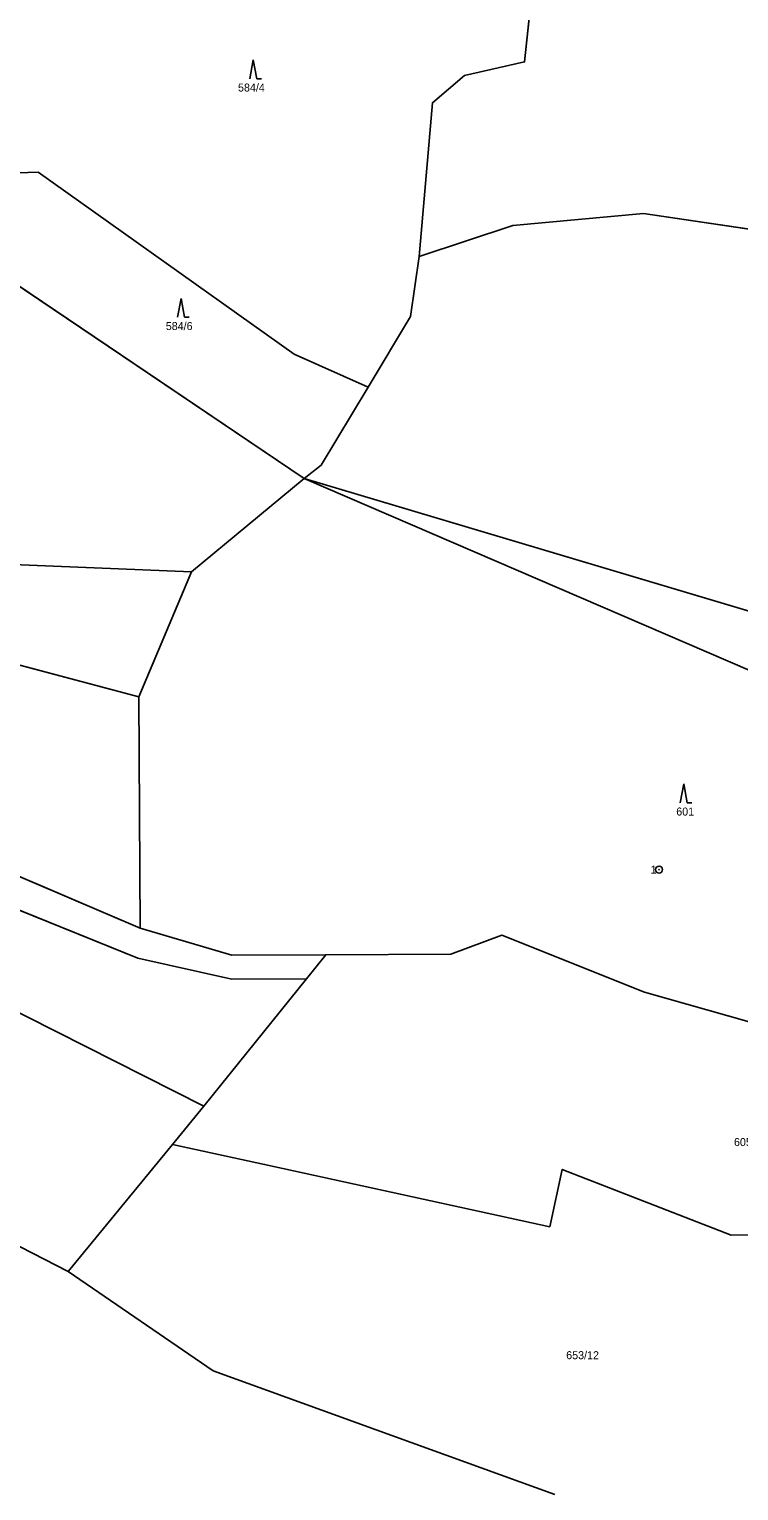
# Model space of a CAD drawing. Extents: x -760642 to -757221, y -1092371 to -1088855.
# Drawn here: x -759878.4 to -759727.7, y -1090551.6 to -1090241.2 of the extents above; entities that cross this region are included whole.
import ezdxf

# ---------------------------------------------------------------- set-up
doc = ezdxf.new("R2010")
doc.units = 0
for name, color, linetype in [('Vrstva 1', 7, 'Continuous'), ('Vrstva 17', 7, 'Continuous'), ('Vrstva 18', 7, 'Continuous'), ('Vrstva 24', 7, 'Continuous'), ('Vrstva 25', 7, 'Continuous'), ('Vrstva 30', 7, 'Continuous')]:
    doc.layers.add(name, color=color, linetype=linetype)

msp = doc.modelspace()

# ---------------------------------------------------------------- linework, layer by layer
at = {"layer": 'Vrstva 1'}
for p, q in [((-759770.83, -1090226.08), (-759773.19, -1090248.13)), ((-759785.94, -1090251.03), (-759792.77, -1090256.83)), ((-759785.94, -1090251.03), (-759773.19, -1090248.13)), ((-759795.55, -1090289.48), (-759792.77, -1090256.83)), ((-759887.2, -1090271.94), (-759876.5, -1090271.55)), ((-759876.5, -1090271.55), (-759822.14, -1090310.19)), ((-759775.69, -1090282.92), (-759747.96, -1090280.33)), ((-759747.96, -1090280.33), (-759657.58, -1090293.67)), ((-759795.55, -1090289.48), (-759775.69, -1090282.92)), ((-759795.55, -1090289.48), (-759797.43, -1090302.2)), ((-759886.74, -1090291.57), (-759819.96, -1090336.6)), ((-759806.41, -1090317.19), (-759797.43, -1090302.2)), ((-759822.14, -1090310.19), (-759806.41, -1090317.19)), ((-759806.41, -1090317.19), (-759816.36, -1090333.8)), ((-759816.36, -1090333.8), (-759819.96, -1090336.6)), ((-759819.96, -1090336.6), (-759843.88, -1090356.4)), ((-759819.96, -1090336.6), (-759815.36, -1090338.58)), ((-759819.96, -1090336.6), (-759703.19, -1090371.43)), ((-759815.36, -1090338.58), (-759712.03, -1090383.13)), ((-759928.46, -1090352.96), (-759843.88, -1090356.4)), ((-759843.88, -1090356.4), (-759855.09, -1090383)), ((-759916.02, -1090366.78), (-759855.09, -1090383)), ((-759854.8, -1090432.12), (-759855.09, -1090383)), ((-759993.69, -1090392.97), (-759841.28, -1090469.87)), ((-759901.58, -1090412.15), (-759854.8, -1090432.12)), ((-759902.82, -1090419.3), (-759855.28, -1090438.48)), ((-759854.8, -1090432.12), (-759835.37, -1090437.86)), ((-759788.87, -1090437.61), (-759777.99, -1090433.62)), ((-759777.99, -1090433.62), (-759747.68, -1090445.67)), ((-759855.28, -1090438.48), (-759835.32, -1090442.96)), ((-759835.37, -1090437.86), (-759815.4, -1090437.75)), ((-759815.4, -1090437.75), (-759819.5, -1090442.84)), ((-759815.4, -1090437.75), (-759788.87, -1090437.61)), ((-759819.5, -1090442.84), (-759841.28, -1090469.87)), ((-759835.32, -1090442.96), (-759819.5, -1090442.84)), ((-759747.68, -1090445.67), (-759686.26, -1090463.12)), ((-759841.28, -1090469.87), (-759847.95, -1090478.02)), ((-759920.78, -1090478.92), (-759870.1, -1090505.04)), ((-759847.95, -1090478.02), (-759870.1, -1090505.04)), ((-759847.95, -1090478.02), (-759828.41, -1090482.29)), ((-759828.41, -1090482.29), (-759767.84, -1090495.53)), ((-759765.17, -1090483.32), (-759767.84, -1090495.53)), ((-759765.17, -1090483.32), (-759729.33, -1090497.29)), ((-759729.33, -1090497.29), (-759658.85, -1090496.57)), ((-759870.1, -1090505.04), (-759839.3, -1090526.12)), ((-759839.3, -1090526.12), (-759766.79, -1090552.4))]:
    msp.add_line(p, q, dxfattribs=at)
at = {"layer": 'Vrstva 24'}
for radius in [0.75, 0.0327]:
    msp.add_circle((-759744.62, -1090419.67), radius, dxfattribs=at)
at = {"layer": 'Vrstva 25'}
for p, q in [((-759830.802, -1090247.729), (-759831.535, -1090251.729)), ((-759830.802, -1090247.729), (-759830.069, -1090251.729)), ((-759830.069, -1090251.729), (-759829.069, -1090251.729)), ((-759846.142, -1090298.379), (-759846.875, -1090302.379)), ((-759846.142, -1090298.379), (-759845.409, -1090302.379)), ((-759845.409, -1090302.379), (-759844.409, -1090302.379)), ((-759739.392, -1090401.479), (-759740.125, -1090405.479)), ((-759739.392, -1090401.479), (-759738.659, -1090405.479)), ((-759738.659, -1090405.479), (-759737.659, -1090405.479))]:
    msp.add_line(p, q, dxfattribs=at)
at = {"layer": 'Vrstva 30'}
for points in [[(-759929.701, -1090260.758), (-759917.51, -1090257.14), (-759898.46, -1090248.84), (-759883.89, -1090257.58), (-759890.91, -1090265.03), (-759887.2, -1090271.94), (-759876.5, -1090271.55), (-759822.14, -1090310.19), (-759806.41, -1090317.19), (-759797.43, -1090302.2), (-759795.55, -1090289.48), (-759792.77, -1090256.83), (-759785.94, -1090251.03), (-759773.19, -1090248.13), (-759770.83, -1090226.08), (-759765.77, -1090190.22), (-759764.68, -1090183.57), (-759879.39, -1090234.5), (-759885.88, -1090220.12), (-759893.47, -1090219.66), (-759895.457, -1090222.272)], [(-759770.83, -1090226.08), (-759773.19, -1090248.13), (-759785.94, -1090251.03), (-759792.77, -1090256.83), (-759795.55, -1090289.48), (-759775.69, -1090282.92), (-759747.96, -1090280.33), (-759657.58, -1090293.67), (-759599.82, -1090303.75), (-759513.38, -1090333.89), (-759496.36, -1090306.31), (-759495.1, -1090295.54), (-759594.27, -1090278.43), (-759591.5, -1090266.26), (-759710.52, -1090239.32), (-759723.09, -1090229.04), (-759731.62, -1090227.14), (-759770.83, -1090226.08)], [(-759819.96, -1090336.6), (-759816.36, -1090333.8), (-759806.41, -1090317.19), (-759822.14, -1090310.19), (-759876.5, -1090271.55), (-759887.2, -1090271.94), (-759887.08, -1090276.95), (-759886.74, -1090291.57), (-759819.96, -1090336.6)], [(-759886.74, -1090291.57), (-759941.98, -1090310.83), (-759938.58, -1090321.86), (-759928.46, -1090352.96), (-759843.88, -1090356.4), (-759819.96, -1090336.6), (-759886.74, -1090291.57)], [(-759843.88, -1090356.4), (-759928.46, -1090352.96), (-759938.58, -1090321.86), (-759975.38, -1090336.95), (-760021.35, -1090335.96), (-760020.35, -1090340.8), (-759973.81, -1090345.64), (-759930.34, -1090360.5), (-759916.02, -1090366.78), (-759855.09, -1090383), (-759843.88, -1090356.4)], [(-759588.61, -1090460.97), (-759712.03, -1090383.13), (-759815.36, -1090338.58), (-759819.96, -1090336.6), (-759843.88, -1090356.4), (-759855.09, -1090383), (-759854.8, -1090432.12), (-759835.37, -1090437.86), (-759815.4, -1090437.75), (-759788.87, -1090437.61), (-759777.99, -1090433.62), (-759747.68, -1090445.67), (-759686.26, -1090463.12), (-759653.21, -1090472.01), (-759615.28, -1090476.85), (-759604.12, -1090473.77), (-759588.61, -1090460.97)], [(-759819.96, -1090336.6), (-759815.36, -1090338.58), (-759712.03, -1090383.13), (-759588.61, -1090460.97), (-759576.6, -1090451.03), (-759703.19, -1090371.43), (-759819.96, -1090336.6)], [(-759819.5, -1090442.84), (-759815.4, -1090437.75), (-759835.37, -1090437.86), (-759854.8, -1090432.12), (-759901.58, -1090412.15), (-759929.79, -1090394.64), (-759932.73, -1090401), (-759902.82, -1090419.3), (-759855.28, -1090438.48), (-759835.32, -1090442.96), (-759819.5, -1090442.84)], [(-759615.28, -1090476.85), (-759653.21, -1090472.01), (-759686.26, -1090463.12), (-759747.68, -1090445.67), (-759777.99, -1090433.62), (-759788.87, -1090437.61), (-759815.4, -1090437.75), (-759819.5, -1090442.84), (-759841.28, -1090469.87), (-759847.95, -1090478.02), (-759828.41, -1090482.29), (-759767.84, -1090495.53), (-759765.17, -1090483.32), (-759729.33, -1090497.29), (-759658.85, -1090496.57), (-759632.54, -1090481.61), (-759615.28, -1090476.85)]]:
    msp.add_lwpolyline(points, dxfattribs=at)

# ---------------------------------------------------------------- texts
at = {"layer": 'Vrstva 17'}
msp.add_text('1', height=1.7, dxfattribs=at).set_placement((-759746.401, -1090420.52))
at = {"layer": 'Vrstva 18'}
for s, p in [('584/4', (-759834.034, -1090254.44)), ('584/6', (-759849.374, -1090305.09)), ('601', (-759740.97, -1090408.19)), ('605/2', (-759728.709, -1090478.38)), ('653/12', (-759764.34, -1090523.64))]:
    msp.add_text(s, height=1.7, dxfattribs=at).set_placement(p)

doc.saveas('drawing.dxf')
